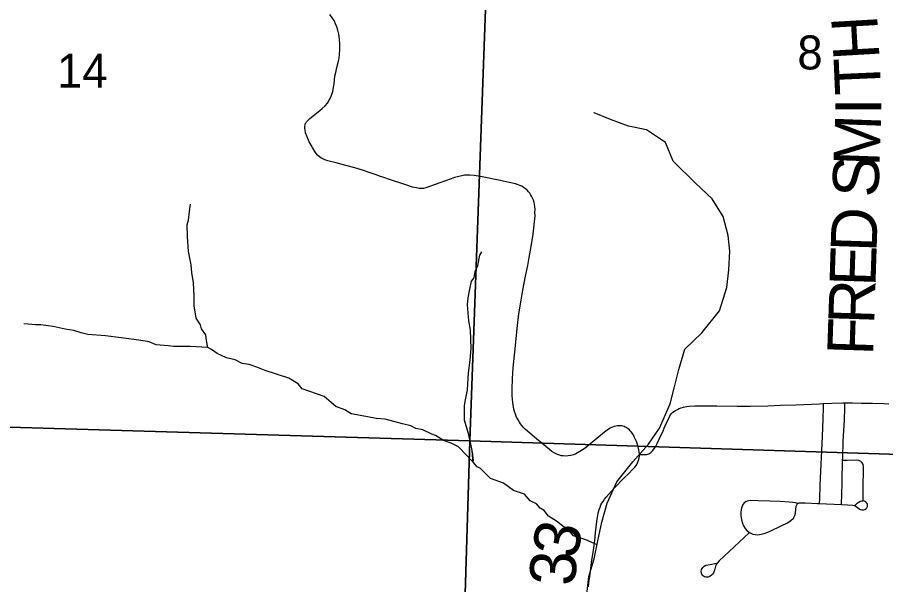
# Model space of a CAD drawing. Extents: x 6.3 to 40.3, y 9 to 31.
# Drawn here: x 10.708 to 11.78, y 26.03 to 26.729 of the extents above; entities that cross this region are included whole.
import ezdxf

# ---------------------------------------------------------------- set-up
doc = ezdxf.new("R2010")
doc.units = 0
for name, color, linetype in [('GM_X_County_Road', 7, 'Continuous'), ('GM_X_County_Road_Text', 7, 'Continuous'), ('GM_X_Minor_River', 7, 'Continuous'), ('GM_X_Section', 7, 'Continuous'), ('GM_X_Section_Text', 7, 'Continuous'), ('GM_X_Township_Road', 7, 'Continuous'), ('GM_X_Township_Road_Text', 7, 'Continuous')]:
    doc.layers.add(name, color=color, linetype=linetype)

msp = doc.modelspace()

# ---------------------------------------------------------------- linework, layer by layer
at = {"layer": 'GM_X_County_Road'}
for points in [[(11.4761, 26.1902), (11.4758, 26.1935), (11.4755, 26.1963), (11.4747, 26.1997), (11.4738, 26.2027), (11.4723, 26.2066), (11.4701, 26.2113), (11.4691, 26.2134), (11.4673, 26.2164), (11.4658, 26.2185), (11.4648, 26.2197), (11.4637, 26.2208), (11.4623, 26.222), (11.4608, 26.223), (11.4596, 26.2237), (11.4585, 26.2242), (11.4572, 26.2248), (11.4556, 26.2252), (11.4541, 26.2256), (11.4523, 26.2258), (11.4506, 26.2258), (11.4489, 26.2256), (11.447, 26.2254), (11.4447, 26.2248), (11.4429, 26.2242), (11.4414, 26.2235), (11.4398, 26.2227), (11.4378, 26.2215), (11.4329, 26.2179), (11.4258, 26.2121), (11.4089, 26.1983), (11.4023, 26.1939), (11.3977, 26.1913), (11.3945, 26.19), (11.3931, 26.1895), (11.3912, 26.189), (11.3883, 26.1886), (11.3851, 26.1883), (11.382, 26.1886), (11.3797, 26.1889), (11.3772, 26.1895), (11.3751, 26.1902), (11.3731, 26.1911), (11.3707, 26.1924), (11.3681, 26.1941), (11.3649, 26.1965), (11.3492, 26.2098), (11.3356, 26.2211), (11.3327, 26.2239), (11.3308, 26.2261), (11.3294, 26.228), (11.3281, 26.2302), (11.3263, 26.2331), (11.3245, 26.2365), (11.323, 26.2399), (11.3219, 26.2435), (11.3212, 26.2461), (11.3205, 26.2491), (11.3197, 26.2543), (11.3192, 26.2586), (11.3189, 26.2629), (11.3189, 26.2708), (11.3193, 26.2839), (11.3204, 26.2972), (11.3219, 26.3128), (11.3255, 26.3493), (11.3274, 26.3637), (11.3301, 26.3805), (11.3323, 26.3931), (11.3355, 26.4103), (11.3383, 26.4236), (11.34, 26.4332), (11.3425, 26.4468), (11.345, 26.4622), (11.3467, 26.4772), (11.3472, 26.4848), (11.3471, 26.4892), (11.3472, 26.4926), (11.3469, 26.4961), (11.3466, 26.4986), (11.3461, 26.5011), (11.3453, 26.504), (11.3442, 26.5064), (11.343, 26.5088), (11.3418, 26.511), (11.3407, 26.5126), (11.3393, 26.5144), (11.3375, 26.5163), (11.3356, 26.5179), (11.3331, 26.5197), (11.3309, 26.5211), (11.3285, 26.5221), (11.3262, 26.523), (11.3233, 26.524), (11.3151, 26.5259), (11.3042, 26.5284), (11.2818, 26.5328), (11.2721, 26.5344), (11.2668, 26.5347), (11.2636, 26.5348), (11.2602, 26.5347), (11.2567, 26.534), (11.2532, 26.5332), (11.2478, 26.5318), (11.2437, 26.5305), (11.2367, 26.528), (11.2299, 26.5253), (11.2124, 26.5191), (11.2095, 26.5185), (11.2065, 26.5184), (11.2042, 26.5185), (11.201, 26.519), (11.1961, 26.5202), (11.1878, 26.5228), (11.1665, 26.53), (11.1618, 26.5316), (11.1553, 26.5337), (11.1524, 26.5347), (11.1436, 26.5378), (11.1343, 26.541), (11.1248, 26.5437), (11.1137, 26.5468), (11.1017, 26.5501), (11.0916, 26.5526), (11.0879, 26.5537), (11.0861, 26.5544), (11.0844, 26.5553), (11.083, 26.5561), (11.0812, 26.5574), (11.0788, 26.5596), (11.0771, 26.5615), (11.0753, 26.5642), (11.0725, 26.569), (11.0707, 26.572), (11.0686, 26.5759), (11.0658, 26.5822), (11.0641, 26.587), (11.0634, 26.5902), (11.0632, 26.5928), (11.0631, 26.5947), (11.0633, 26.5964), (11.0637, 26.598), (11.0644, 26.5991), (11.0652, 26.6004), (11.0665, 26.6019), (11.0692, 26.6047), (11.0775, 26.6112), (11.0818, 26.6147), (11.0846, 26.6171), (11.0882, 26.6205), (11.0909, 26.6237), (11.0933, 26.6272), (11.0944, 26.6292), (11.0957, 26.6323), (11.0969, 26.6355), (11.0976, 26.6379), (11.0981, 26.6408), (11.0991, 26.6475), (11.1003, 26.6567), (11.1012, 26.6615), (11.1026, 26.6676), (11.105, 26.6772), (11.1056, 26.6801), (11.106, 26.6832), (11.1064, 26.6899), (11.1064, 26.6966), (11.106, 26.7027), (11.1051, 26.7088), (11.104, 26.7136), (11.1027, 26.7176), (11.1011, 26.7216), (11.0991, 26.7254), (11.0969, 26.729), (11.0941, 26.733)], [(11.4133, 26.0273), (11.4138, 26.0322), (11.4147, 26.0395), (11.4157, 26.0467), (11.4166, 26.0535), (11.4171, 26.0571), (11.4179, 26.0626), (11.4189, 26.0696), (11.4196, 26.0751), (11.4209, 26.0842), (11.422, 26.0939), (11.4236, 26.1077), (11.4253, 26.118), (11.4264, 26.1226), (11.4274, 26.1255), (11.4286, 26.1282), (11.4298, 26.1305), (11.4312, 26.1326), (11.4331, 26.1352), (11.4352, 26.1379), (11.4449, 26.1489), (11.4568, 26.1613), (11.463, 26.1671), (11.4677, 26.1717), (11.4705, 26.1749), (11.4723, 26.1774), (11.4737, 26.18), (11.4747, 26.1821), (11.4755, 26.1841), (11.4758, 26.1861), (11.4761, 26.1883), (11.4761, 26.1902)]]:
    msp.add_lwpolyline(points, dxfattribs=at)
at = {"layer": 'GM_X_Minor_River'}
for points in [[(11.4094, 26.0032), (11.4136, 26.0398), (11.42, 26.0617), (11.4249, 26.084), (11.4298, 26.107), (11.4363, 26.1304), (11.448, 26.1568), (11.4681, 26.1814), (11.4874, 26.2033), (11.501, 26.2229), (11.5139, 26.2527), (11.5195, 26.2738), (11.5245, 26.2953), (11.532, 26.3202), (11.5532, 26.3403), (11.5748, 26.3674), (11.5839, 26.3961), (11.5862, 26.418), (11.5877, 26.441), (11.5854, 26.4603), (11.5794, 26.4837), (11.5657, 26.5056), (11.5453, 26.5248), (11.5176, 26.552), (11.5082, 26.575), (11.4847, 26.5909), (11.4624, 26.5954), (11.4404, 26.6033), (11.4203, 26.6116), (11.42, 26.612)], [(11.2709, 26.1811), (11.2529, 26.1999), (11.2437, 26.2044), (11.2342, 26.2077), (11.2242, 26.2137), (11.2197, 26.2155), (11.2086, 26.2207), (11.2002, 26.2225), (11.1941, 26.2259), (11.1835, 26.228), (11.1621, 26.2339), (11.1511, 26.2349), (11.1317, 26.2385), (11.1203, 26.2406), (11.1126, 26.2455), (11.1012, 26.2496), (11.087, 26.2619), (11.0599, 26.2715), (11.0549, 26.2775), (11.0435, 26.2846), (11.0141, 26.2938), (11.0038, 26.2979), (10.9943, 26.3012), (10.9859, 26.3026), (10.9772, 26.3071), (10.9665, 26.3096), (10.9547, 26.3148), (10.9478, 26.3197), (10.9432, 26.3223), (10.9416, 26.331), (10.9408, 26.3378), (10.9354, 26.3454), (10.9342, 26.3503), (10.9288, 26.3586), (10.9263, 26.3738), (10.9266, 26.3859), (10.9256, 26.4022), (10.9236, 26.4147), (10.9227, 26.4242), (10.9195, 26.4405), (10.9182, 26.4587), (10.9181, 26.464), (10.9177, 26.4694), (10.918, 26.4735), (10.9195, 26.4792), (10.9202, 26.4865), (10.9212, 26.4933), (10.9219, 26.499)], [(11.4238, 26.0788), (11.4098, 26.085), (11.3945, 26.0902), (11.3911, 26.0947), (11.3735, 26.1082), (11.3639, 26.1145), (11.3585, 26.1213), (11.3535, 26.1243), (11.3489, 26.1295), (11.3413, 26.1333), (11.3344, 26.1415), (11.3207, 26.1459), (11.3084, 26.1549), (11.2924, 26.1608), (11.2801, 26.1729), (11.2759, 26.1751), (11.2709, 26.1811), (11.2701, 26.1895), (11.2696, 26.1955), (11.2656, 26.2145), (11.2636, 26.2217), (11.2601, 26.2326), (11.2603, 26.2509), (11.2614, 26.2577), (11.2639, 26.2703), (11.2652, 26.2912), (11.2673, 26.3068), (11.2683, 26.3212), (11.2677, 26.3436), (11.2653, 26.3553), (11.2639, 26.3751), (11.2646, 26.3834), (11.2667, 26.3941), (11.2689, 26.404), (11.2719, 26.4082), (11.2733, 26.4162), (11.2767, 26.4234), (11.2792, 26.436), (11.2814, 26.4402)], [(10.9432, 26.3223), (10.9215, 26.3236), (10.9109, 26.3235), (10.901, 26.3237), (10.8946, 26.3244), (10.8794, 26.3258), (10.871, 26.3291), (10.8584, 26.3313), (10.8364, 26.3344), (10.817, 26.3369), (10.7953, 26.3382), (10.7869, 26.3404), (10.7778, 26.3433), (10.7671, 26.3451), (10.7523, 26.3484), (10.7462, 26.349), (10.7371, 26.3501), (10.7306, 26.3504), (10.7215, 26.3511), (10.7162, 26.3514)], [(11.2698, 26.1937), (11.2708, 26.1825)]]:
    msp.add_lwpolyline(points, dxfattribs=at)
at = {"layer": 'GM_X_Section'}
for points in [[(10.3113, 27.232), (11.3031, 27.2038), (11.2666, 26.2073), (10.2824, 26.2364)], [(11.3031, 27.2038), (12.2889, 27.1733), (12.2638, 26.3888), (12.2636, 26.3793), (12.255, 26.3481), (12.2521, 26.3409), (12.2402, 26.3255), (12.2343, 26.3163), (12.218, 26.293), (12.2028, 26.2726), (12.1883, 26.2538), (12.1742, 26.2366), (12.1608, 26.2201), (12.1526, 26.2116), (12.1361, 26.1988), (12.0826, 26.1813), (11.2666, 26.2073)], [(10.2824, 26.2364), (11.2666, 26.2073), (11.242, 25.3993), (11.2405, 25.3466), (11.2394, 25.3243), (11.2143, 25.2557), (11.1962, 25.2251), (10.2864, 25.2447)]]:
    msp.add_lwpolyline(points, close=True, dxfattribs=at)
msp.add_lwpolyline([(11.242, 25.3993), (11.2666, 26.2073), (12.0826, 26.1813)], dxfattribs=at)
at = {"layer": 'GM_X_Township_Road'}
msp.add_line((11.6978, 26.1298), (11.7256, 26.1287), dxfattribs=at)
for points in [[(11.4761, 26.1902), (11.4816, 26.1902), (11.4839, 26.1902), (11.4851, 26.1904), (11.4864, 26.1907), (11.4876, 26.1912), (11.4888, 26.1919), (11.49, 26.1929), (11.4922, 26.1949), (11.4938, 26.1969), (11.4957, 26.2), (11.4979, 26.2039), (11.5005, 26.2093), (11.5054, 26.2195), (11.5067, 26.2229), (11.5079, 26.2256), (11.5104, 26.2309), (11.5114, 26.233), (11.5137, 26.2382), (11.5153, 26.2407), (11.5168, 26.2422), (11.5185, 26.2434), (11.5206, 26.2447), (11.5231, 26.246), (11.5251, 26.247), (11.5276, 26.248), (11.5303, 26.2489), (11.5321, 26.2493), (11.5347, 26.2497), (11.5376, 26.2499), (11.5444, 26.2503), (11.5525, 26.2504), (11.5717, 26.2502), (11.5966, 26.25), (11.6127, 26.2499), (11.6344, 26.2503), (11.6498, 26.251), (11.669, 26.2518), (11.6982, 26.2529), (11.7029, 26.2532)], [(11.7029, 26.2532), (11.7028, 26.2484), (11.7025, 26.2342), (11.7015, 26.2125), (11.6988, 26.1524), (11.6981, 26.1362), (11.6978, 26.1298)], [(11.7029, 26.2532), (11.7137, 26.2537), (11.7273, 26.2542), (11.7297, 26.2542)], [(11.7256, 26.1287), (11.7256, 26.1317), (11.7257, 26.1391), (11.7261, 26.157), (11.7268, 26.1829), (11.7269, 26.1866), (11.7277, 26.2064), (11.7291, 26.233), (11.7295, 26.2473), (11.7297, 26.2542)], [(11.7297, 26.2542), (11.7391, 26.2542), (11.7503, 26.2538), (11.7639, 26.2535), (11.7776, 26.2532), (11.784, 26.253)], [(11.7414, 26.1273), (11.7434, 26.1262), (11.7469, 26.1236), (11.7478, 26.1229), (11.749, 26.1224), (11.7508, 26.122), (11.7527, 26.1221), (11.7544, 26.1227), (11.756, 26.1238), (11.7566, 26.1245), (11.7571, 26.1253), (11.7574, 26.1264), (11.7577, 26.1276), (11.7577, 26.1285), (11.7575, 26.1294), (11.7569, 26.1305), (11.7556, 26.1318), (11.754, 26.1328), (11.752, 26.1332), (11.752, 26.1372), (11.7521, 26.1508), (11.7528, 26.1713), (11.7525, 26.1756), (11.752, 26.178), (11.7509, 26.1802), (11.7492, 26.1819), (11.7469, 26.1828), (11.7438, 26.1833), (11.7326, 26.183), (11.7268, 26.1829)], [(11.6716, 26.1299), (11.6686, 26.1307), (11.6652, 26.1312), (11.661, 26.1316), (11.6499, 26.1323), (11.6369, 26.1328), (11.6226, 26.1334), (11.6132, 26.1335), (11.609, 26.1327), (11.6073, 26.132), (11.6054, 26.1306), (11.6032, 26.1277), (11.6019, 26.1241), (11.6013, 26.1198), (11.6013, 26.1148), (11.602, 26.1099), (11.6031, 26.1057), (11.6047, 26.1023), (11.6067, 26.0992), (11.6092, 26.0964), (11.6121, 26.0941)], [(11.6121, 26.0941), (11.616, 26.0923), (11.619, 26.0917), (11.6221, 26.0915), (11.6264, 26.092), (11.6312, 26.0933), (11.6376, 26.0959), (11.651, 26.1023), (11.6587, 26.1063), (11.663, 26.1089), (11.6661, 26.1119), (11.6679, 26.1151), (11.6686, 26.1181), (11.6689, 26.1225), (11.6696, 26.1268), (11.6707, 26.129), (11.6716, 26.1299), (11.6731, 26.1308), (11.6743, 26.1309), (11.6805, 26.1306), (11.696, 26.1299), (11.6978, 26.1298)], [(11.7256, 26.1287), (11.7327, 26.1284), (11.7395, 26.1279), (11.7414, 26.1273)], [(11.7414, 26.1273), (11.7434, 26.1292), (11.7447, 26.1303), (11.7459, 26.1312), (11.748, 26.1325), (11.7491, 26.1328), (11.7505, 26.1332), (11.752, 26.1332)], [(11.6121, 26.0941), (11.6116, 26.0936), (11.5746, 26.0593), (11.5718, 26.0565), (11.5707, 26.0547), (11.57, 26.0521), (11.5693, 26.049), (11.5685, 26.0463), (11.5676, 26.0446), (11.5664, 26.043), (11.565, 26.0414), (11.5631, 26.04), (11.5609, 26.0393), (11.5582, 26.0393), (11.5562, 26.0396), (11.555, 26.0403), (11.5538, 26.0414), (11.5531, 26.0426), (11.5525, 26.0442), (11.5522, 26.046), (11.5526, 26.0487), (11.5542, 26.0511), (11.556, 26.0525), (11.5582, 26.0537), (11.5634, 26.0549), (11.571, 26.0563)]]:
    msp.add_lwpolyline(points, dxfattribs=at)

# ---------------------------------------------------------------- texts
at = {"layer": 'GM_X_County_Road_Text'}
for rotation, p in [(78.6888, (11.3984, 26.0601)), (86.9763, (11.3968, 26.0276))]:
    msp.add_text('3', height=0.0568, rotation=rotation, dxfattribs=at).set_placement(p)
at = {"layer": 'GM_X_Section_Text'}
for s, height, p in [('8', 0.0419, (11.671, 26.6652)), ('14', 0.04186, (10.7573, 26.6426))]:
    msp.add_text(s, height=height, rotation=0, dxfattribs=at).set_placement(p)
at = {"layer": 'GM_X_Township_Road_Text'}
for s, rotation, p in [('H', 93.3218, (11.7725, 26.6785)), ('T', 92.4907, (11.7744, 26.6351)), ('I', 90.097, (11.7745, 26.6092)), ('M', 87.9025, (11.7722, 26.5452)), ('S', 88.1086, (11.7709, 26.5069)), ('D', 88.1084, (11.7687, 26.4395)), ('E', 88.1054, (11.7673, 26.397)), ('R', 88.1111, (11.7658, 26.3504)), ('F', 88.1086, (11.7645, 26.312))]:
    msp.add_text(s, height=0.0568, rotation=rotation, dxfattribs=at).set_placement(p)

doc.saveas('drawing.dxf')
